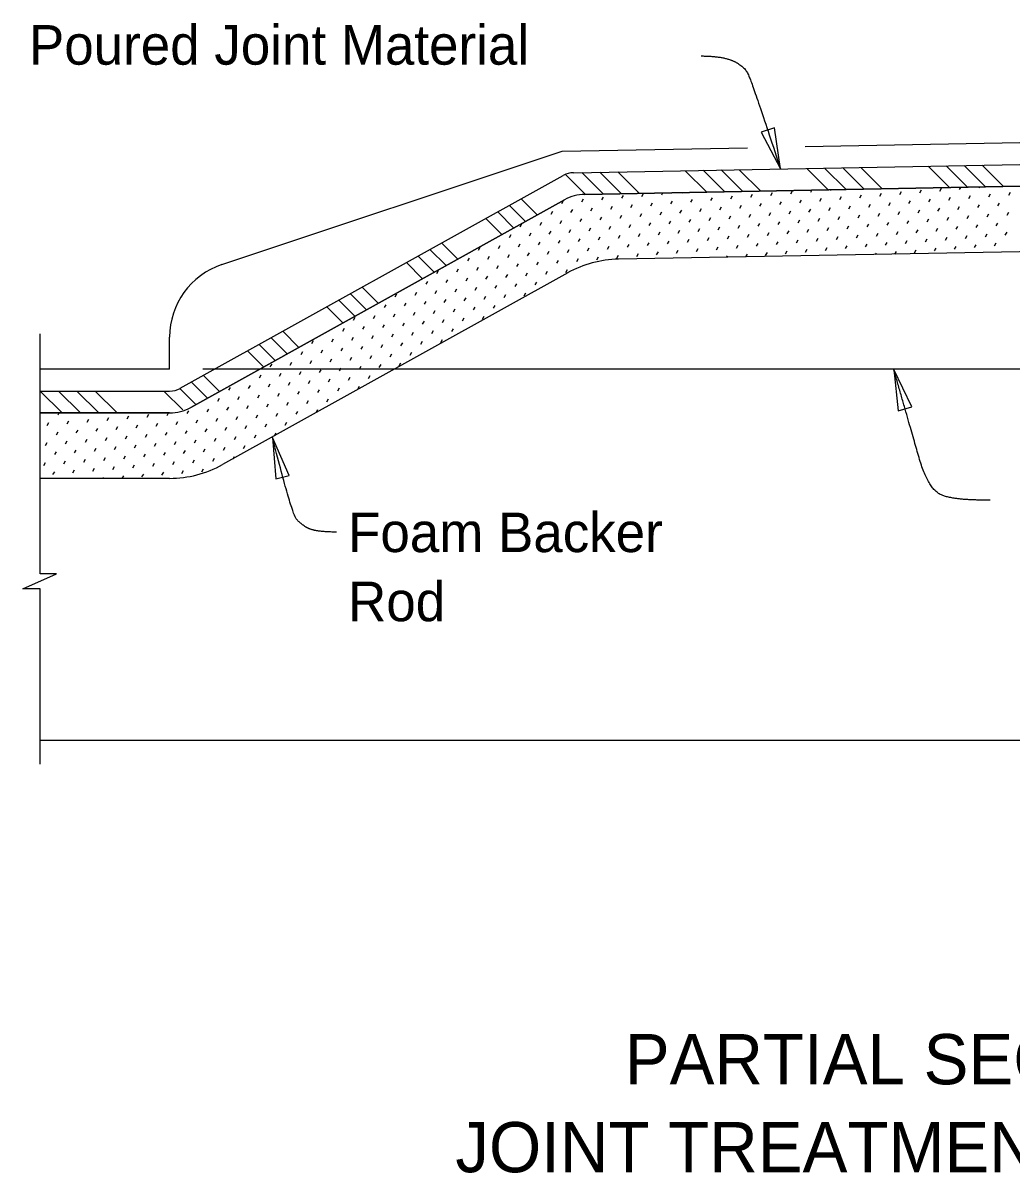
# Model space of a CAD drawing. Extents: x -7.9 to 27, y -3.1 to 14.6.
# Drawn here: x 5.225 to 7.115, y 7.064 to 9.26 of the extents above; entities that cross this region are included whole.
import ezdxf

# ---------------------------------------------------------------- set-up
doc = ezdxf.new("R2010")
doc.units = 0
for name, color, linetype in [('Border', 7, 'Continuous'), ('Patterning', 7, 'Continuous'), ('PlotBorder_dp', 7, 'Continuous'), ('SupstrConc_h', 7, 'Continuous'), ('TextMisc', 7, 'Continuous')]:
    doc.layers.add(name, color=color, linetype=linetype)

msp = doc.modelspace()

# ---------------------------------------------------------------- linework, layer by layer
at = {"layer": 'Patterning'}
for p, q in [((6.7193, 9.0243), (7.7, 9.0424)), ((5.605, 8.7989), (6.2554, 9.0156)), ((6.2554, 9.0157), (6.6094, 9.0222)), ((5.5054, 8.5989), (5.5054, 8.6605)), ((5.2585, 7.8906), (10.1444, 7.8906))]:
    msp.add_line(p, q, dxfattribs=at)
msp.add_lwpolyline([(5.5054, 8.599), (5.2585, 8.599)], dxfattribs=at)
msp.add_arc((5.6512, 8.6606), 0.1458, 108.4349, 180, dxfattribs=at)
at = {"layer": 'PlotBorder_dp'}
for points in [[(6.6724, 8.9817), (6.6606, 9.06), (6.6355, 9.0518)], [(6.8886, 8.5984), (6.8974, 8.5197), (6.9229, 8.527)], [(5.7022, 8.4684), (5.7084, 8.3895), (5.7341, 8.3959)]]:
    msp.add_lwpolyline(points, close=True, dxfattribs=at)
msp.add_lwpolyline([(5.2585, 7.8445), (5.2585, 8.1797), (5.2254, 8.1797), (5.2894, 8.208), (5.2585, 8.208), (5.2585, 8.6664)], dxfattribs=at)
for points in [[(6.5206, 9.1974), (6.5602, 9.1974), (6.6031, 9.1787), (6.6185, 9.1457), (6.6724, 8.9817)], [(7.0728, 8.3491), (7.001, 8.3482), (6.9538, 8.3718), (6.9198, 8.4899), (6.8887, 8.5985)], [(5.8243, 8.288), (5.7847, 8.288), (5.7561, 8.3023), (5.7385, 8.3243), (5.7022, 8.4684)]]:
    msp.add_open_spline(points, degree=2, dxfattribs=at)
at = {"layer": 'SupstrConc_h'}
msp.add_lwpolyline([(9.1821, 8.599), (5.5686, 8.599)], dxfattribs=at)
at = {"layer": 'TextMisc'}
for p, q in [((6.2769, 8.9744), (7.6992, 9.0007)), ((6.8255, 8.9845), (6.8664, 8.9436)), ((6.9542, 8.9869), (6.9952, 8.946)), ((6.9886, 8.9876), (7.0295, 8.9466)), ((7.0229, 8.9882), (7.0639, 8.9472)), ((7.0573, 8.9888), (7.0983, 8.9479)), ((5.5257, 8.5626), (6.2574, 8.9691)), ((6.2623, 8.9704), (6.2996, 8.9331)), ((6.293, 8.9747), (6.334, 8.9337)), ((6.3274, 8.9753), (6.3683, 8.9344)), ((6.3618, 8.9759), (6.4027, 8.935)), ((6.4905, 8.9783), (6.5315, 8.9374)), ((6.5249, 8.979), (6.5658, 8.938)), ((6.5592, 8.9796), (6.6002, 8.9387)), ((6.5936, 8.9802), (6.6346, 8.9393)), ((6.7224, 8.9826), (6.7633, 8.9417)), ((6.7567, 8.9833), (6.7977, 8.9423)), ((6.7911, 8.9839), (6.832, 8.9429)), ((7.6985, 8.959), (6.2985, 8.9331)), ((6.2985, 8.9331), (7.6985, 8.959)), ((6.73, 8.9373), (6.7321, 8.9411)), ((6.7681, 8.9406), (6.7688, 8.9418)), ((6.9382, 8.9361), (6.9414, 8.9417)), ((6.9764, 8.9393), (6.9796, 8.9449)), ((7.0145, 8.9426), (7.0167, 8.9464)), ((7.0527, 8.9458), (7.0534, 8.9471)), ((6.2595, 8.9226), (5.5459, 8.5261)), ((5.5459, 8.5261), (6.2595, 8.9226)), ((6.1771, 8.9245), (6.2077, 8.8938)), ((6.2547, 8.9159), (6.2579, 8.9215)), ((6.2928, 8.9191), (6.2961, 8.9247)), ((6.331, 8.9224), (6.3342, 8.928)), ((6.3691, 8.9256), (6.3724, 8.9312)), ((6.4073, 8.9289), (6.4105, 8.9345)), ((6.4454, 8.9321), (6.4476, 8.9358)), ((6.4629, 8.9147), (6.4661, 8.9202)), ((6.4836, 8.9353), (6.4843, 8.9365)), ((6.501, 8.9179), (6.5043, 8.9235)), ((6.5392, 8.9211), (6.5424, 8.9267)), ((6.5774, 8.9244), (6.5806, 8.93)), ((6.6155, 8.9276), (6.6188, 8.9332)), ((6.6537, 8.9309), (6.6569, 8.9365)), ((6.6711, 8.9134), (6.6744, 8.919)), ((6.6918, 8.9341), (6.6951, 8.9397)), ((6.7093, 8.9166), (6.7125, 8.9222)), ((6.7474, 8.9199), (6.7507, 8.9255)), ((6.7856, 8.9231), (6.7888, 8.9287)), ((6.8237, 8.9264), (6.827, 8.932)), ((6.8619, 8.9296), (6.8651, 8.9352)), ((6.9, 8.9328), (6.9033, 8.9384)), ((6.9175, 8.9154), (6.9207, 8.921)), ((6.9557, 8.9186), (6.9589, 8.9242)), ((6.9938, 8.9219), (6.9971, 8.9275)), ((7.032, 8.9251), (7.0352, 8.9307)), ((7.0701, 8.9284), (7.0734, 8.9339)), ((7.1083, 8.9316), (7.1115, 8.9372)), ((6.1321, 8.8995), (6.1627, 8.8688)), ((6.1546, 8.912), (6.1852, 8.8813)), ((6.234, 8.8952), (6.2372, 8.9008)), ((6.2721, 8.8984), (6.2754, 8.904)), ((6.3103, 8.9017), (6.3135, 8.9073)), ((6.3484, 8.9049), (6.3517, 8.9105)), ((6.3866, 8.9082), (6.3898, 8.9138)), ((6.4247, 8.9114), (6.428, 8.917)), ((6.4422, 8.894), (6.4454, 8.8996)), ((6.4803, 8.8972), (6.4836, 8.9028)), ((6.5185, 8.9004), (6.5217, 8.906)), ((6.5567, 8.9037), (6.5599, 8.9093)), ((6.5948, 8.9069), (6.5981, 8.9125)), ((6.633, 8.9102), (6.6362, 8.9158)), ((6.6504, 8.8927), (6.6537, 8.8983)), ((6.6886, 8.8959), (6.6918, 8.9015)), ((6.7267, 8.8992), (6.73, 8.9048)), ((6.7649, 8.9024), (6.7681, 8.908)), ((6.803, 8.9057), (6.8063, 8.9113)), ((6.8412, 8.9089), (6.8444, 8.9145)), ((6.8587, 8.8914), (6.8619, 8.897)), ((6.8793, 8.9121), (6.8826, 8.9177)), ((6.8968, 8.8947), (6.9, 8.9003)), ((6.935, 8.8979), (6.9382, 8.9035)), ((6.9731, 8.9012), (6.9764, 8.9068)), ((7.0113, 8.9044), (7.0145, 8.91)), ((7.0494, 8.9077), (7.0527, 8.9133)), ((7.0876, 8.9109), (7.0908, 8.9165)), ((7.105, 8.8934), (7.1083, 8.899)), ((6.1096, 8.887), (6.1402, 8.8563)), ((6.1751, 8.8713), (6.1784, 8.8769)), ((6.2133, 8.8745), (6.2165, 8.8801)), ((6.2514, 8.8777), (6.2547, 8.8833)), ((6.2896, 8.881), (6.2928, 8.8866)), ((6.3277, 8.8842), (6.331, 8.8898)), ((6.3659, 8.8875), (6.3691, 8.8931)), ((6.3833, 8.87), (6.3866, 8.8756)), ((6.404, 8.8907), (6.4073, 8.8963)), ((6.4215, 8.8733), (6.4247, 8.8789)), ((6.4597, 8.8765), (6.4629, 8.8821)), ((6.4978, 8.8797), (6.501, 8.8853)), ((6.536, 8.883), (6.5392, 8.8886)), ((6.5741, 8.8862), (6.5774, 8.8918)), ((6.6123, 8.8895), (6.6155, 8.8951)), ((6.6297, 8.872), (6.633, 8.8776)), ((6.6679, 8.8752), (6.6711, 8.8808)), ((6.706, 8.8785), (6.7093, 8.8841)), ((6.7442, 8.8817), (6.7474, 8.8873)), ((6.7823, 8.885), (6.7856, 8.8906)), ((6.8205, 8.8882), (6.8237, 8.8938)), ((6.838, 8.8708), (6.8412, 8.8763)), ((6.8761, 8.874), (6.8793, 8.8796)), ((6.9143, 8.8772), (6.9175, 8.8828)), ((6.9524, 8.8805), (6.9557, 8.8861)), ((6.9906, 8.8837), (6.9938, 8.8893)), ((7.0287, 8.887), (7.032, 8.8926)), ((7.0462, 8.8695), (7.0494, 8.8751)), ((7.0669, 8.8902), (7.0701, 8.8958)), ((7.0843, 8.8727), (7.0876, 8.8783)), ((6.1544, 8.8506), (6.1577, 8.8562)), ((6.1926, 8.8538), (6.1958, 8.8594)), ((6.2307, 8.8571), (6.234, 8.8626)), ((6.2689, 8.8603), (6.2721, 8.8659)), ((6.307, 8.8635), (6.3103, 8.8691)), ((6.3452, 8.8668), (6.3484, 8.8724)), ((6.3626, 8.8493), (6.3659, 8.8549)), ((6.4008, 8.8526), (6.404, 8.8582)), ((6.439, 8.8558), (6.4422, 8.8614)), ((6.4771, 8.859), (6.4803, 8.8646)), ((6.5153, 8.8623), (6.5185, 8.8679)), ((6.5534, 8.8655), (6.5567, 8.8711)), ((6.5709, 8.8481), (6.5741, 8.8537)), ((6.5916, 8.8688), (6.5948, 8.8744)), ((6.609, 8.8513), (6.6123, 8.8569)), ((6.6472, 8.8545), (6.6504, 8.8601)), ((6.6853, 8.8578), (6.6886, 8.8634)), ((6.7235, 8.861), (6.7267, 8.8666)), ((6.7616, 8.8643), (6.7649, 8.8699)), ((6.7998, 8.8675), (6.803, 8.8731)), ((6.8173, 8.8501), (6.8205, 8.8557)), ((6.8554, 8.8533), (6.8587, 8.8589)), ((6.8936, 8.8565), (6.8968, 8.8621)), ((6.9317, 8.8598), (6.935, 8.8654)), ((6.9699, 8.863), (6.9731, 8.8686)), ((7.008, 8.8663), (7.0113, 8.8719)), ((7.0255, 8.8488), (7.0287, 8.8544)), ((7.0636, 8.852), (7.0669, 8.8576)), ((7.1018, 8.8553), (7.105, 8.8609)), ((6.0253, 8.8401), (6.0559, 8.8095)), ((6.0956, 8.8266), (6.0988, 8.8322)), ((6.1337, 8.8299), (6.137, 8.8355)), ((6.1719, 8.8331), (6.1751, 8.8387)), ((6.21, 8.8364), (6.2133, 8.842)), ((6.2482, 8.8396), (6.2514, 8.8452)), ((6.2863, 8.8428), (6.2896, 8.8484)), ((6.3038, 8.8254), (6.307, 8.831)), ((6.3245, 8.8461), (6.3277, 8.8517)), ((6.3419, 8.8286), (6.3452, 8.8342)), ((7.6961, 8.8339), (6.3631, 8.8092)), ((6.3801, 8.8319), (6.3833, 8.8375)), ((6.4183, 8.8351), (6.4215, 8.8407)), ((6.4564, 8.8383), (6.4597, 8.8439)), ((6.4946, 8.8416), (6.4978, 8.8472)), ((6.5327, 8.8448), (6.536, 8.8504)), ((6.5502, 8.8274), (6.5534, 8.833)), ((6.5883, 8.8306), (6.5916, 8.8362)), ((6.6265, 8.8338), (6.6297, 8.8394)), ((6.6646, 8.8371), (6.6679, 8.8427)), ((6.7028, 8.8403), (6.706, 8.8459)), ((6.7409, 8.8436), (6.7442, 8.8492)), ((6.7584, 8.8261), (6.7616, 8.8317)), ((6.7791, 8.8468), (6.7823, 8.8524)), ((6.7966, 8.8294), (6.7998, 8.835)), ((6.8347, 8.8326), (6.838, 8.8382)), ((6.8729, 8.8358), (6.8761, 8.8414)), ((6.911, 8.8391), (6.9143, 8.8447)), ((6.9492, 8.8423), (6.9524, 8.8479)), ((6.9873, 8.8456), (6.9906, 8.8512)), ((7.0048, 8.8281), (7.008, 8.8337)), ((7.0429, 8.8313), (7.0462, 8.8369)), ((7.0811, 8.8346), (7.0843, 8.8402)), ((5.9803, 8.8151), (6.0109, 8.7845)), ((6.0028, 8.8276), (6.0334, 8.797)), ((6.0749, 8.8059), (6.0781, 8.8115)), ((6.113, 8.8092), (6.1163, 8.8148)), ((6.1512, 8.8124), (6.1544, 8.818)), ((6.1893, 8.8157), (6.1926, 8.8213)), ((6.2275, 8.8189), (6.2307, 8.8245)), ((6.2656, 8.8221), (6.2689, 8.8277)), ((6.2831, 8.8047), (6.2863, 8.8103)), ((6.3212, 8.8079), (6.3245, 8.8135)), ((6.3594, 8.8112), (6.3626, 8.8168)), ((6.3976, 8.8144), (6.4008, 8.82)), ((6.4357, 8.8176), (6.439, 8.8232)), ((6.4739, 8.8209), (6.4771, 8.8265)), ((6.512, 8.8241), (6.5153, 8.8297)), ((6.5695, 8.8131), (6.5709, 8.8155)), ((6.6061, 8.8137), (6.609, 8.8187)), ((6.6439, 8.8164), (6.6472, 8.822)), ((6.6821, 8.8196), (6.6853, 8.8252)), ((6.7202, 8.8229), (6.7235, 8.8285)), ((6.854, 8.8183), (6.8554, 8.8207)), ((6.8907, 8.819), (6.8936, 8.824)), ((6.9285, 8.8216), (6.9317, 8.8272)), ((6.9666, 8.8249), (6.9699, 8.8305)), ((5.9578, 8.8026), (5.9884, 8.772)), ((6.016, 8.782), (6.0193, 8.7876)), ((6.0542, 8.7852), (6.0574, 8.7908)), ((6.0923, 8.7885), (6.0956, 8.7941)), ((6.1305, 8.7917), (6.1337, 8.7973)), ((6.1686, 8.795), (6.1719, 8.8006)), ((6.2068, 8.7982), (6.21, 8.8038)), ((6.2449, 8.8014), (6.2482, 8.807)), ((6.2624, 8.784), (6.2656, 8.7896)), ((6.2658, 8.7831), (5.6066, 8.4168)), ((5.9953, 8.7613), (5.9986, 8.7669)), ((6.0335, 8.7645), (6.0367, 8.7701)), ((6.0716, 8.7678), (6.0749, 8.7734)), ((6.1098, 8.771), (6.113, 8.7766)), ((6.1479, 8.7743), (6.1512, 8.7799)), ((6.1861, 8.7775), (6.1893, 8.7831)), ((6.2035, 8.76), (6.2068, 8.7656)), ((6.2242, 8.7807), (6.2275, 8.7863)), ((5.851, 8.7433), (5.8816, 8.7126)), ((5.8735, 8.7558), (5.9041, 8.7251)), ((5.9365, 8.7374), (5.9397, 8.743)), ((5.9746, 8.7406), (5.9779, 8.7462)), ((6.0128, 8.7438), (6.016, 8.7494)), ((6.0509, 8.7471), (6.0542, 8.7527)), ((6.0891, 8.7503), (6.0923, 8.7559)), ((6.1272, 8.7536), (6.1305, 8.7592)), ((6.1654, 8.7568), (6.1686, 8.7624)), ((6.1828, 8.7393), (6.1861, 8.7449)), ((5.8285, 8.7308), (5.8591, 8.7001)), ((5.9158, 8.7167), (5.919, 8.7223)), ((5.9539, 8.7199), (5.9572, 8.7255)), ((5.9921, 8.7231), (5.9953, 8.7287)), ((6.0302, 8.7264), (6.0335, 8.732)), ((6.0684, 8.7296), (6.0716, 8.7352)), ((6.1065, 8.7329), (6.1098, 8.7385)), ((6.124, 8.7154), (6.1272, 8.721)), ((6.1447, 8.7361), (6.1479, 8.7417)), ((5.806, 8.7183), (5.8366, 8.6876)), ((5.8951, 8.696), (5.8983, 8.7016)), ((5.9332, 8.6992), (5.9365, 8.7048)), ((5.9714, 8.7024), (5.9746, 8.708)), ((6.0095, 8.7057), (6.0128, 8.7113)), ((6.0477, 8.7089), (6.0509, 8.7145)), ((6.0858, 8.7122), (6.0891, 8.7178)), ((6.1033, 8.6947), (6.1065, 8.7003)), ((5.8362, 8.672), (5.8395, 8.6776)), ((5.8569, 8.6927), (5.8602, 8.6983)), ((5.8744, 8.6753), (5.8776, 8.6809)), ((5.9125, 8.6785), (5.9158, 8.6841)), ((5.9507, 8.6817), (5.9539, 8.6873)), ((5.9888, 8.685), (5.9921, 8.6906)), ((6.027, 8.6882), (6.0302, 8.6938)), ((6.0651, 8.6915), (6.0684, 8.6971)), ((5.6992, 8.659), (5.7298, 8.6283)), ((5.7217, 8.6715), (5.7523, 8.6408)), ((5.8155, 8.6513), (5.8188, 8.6569)), ((5.8537, 8.6546), (5.8569, 8.6602)), ((5.8918, 8.6578), (5.8951, 8.6634)), ((5.93, 8.6611), (5.9332, 8.6666)), ((5.9681, 8.6643), (5.9714, 8.6699)), ((6.0063, 8.6675), (6.0095, 8.6731)), ((6.0237, 8.6501), (6.027, 8.6557)), ((6.0444, 8.6708), (6.0477, 8.6764)), ((5.6542, 8.634), (5.6848, 8.6033)), ((5.6767, 8.6465), (5.7073, 8.6158)), ((5.7567, 8.6274), (5.7599, 8.633)), ((5.7774, 8.6481), (5.7806, 8.6537)), ((5.7948, 8.6306), (5.7981, 8.6362)), ((5.833, 8.6339), (5.8362, 8.6395)), ((5.8711, 8.6371), (5.8744, 8.6427)), ((5.9093, 8.6404), (5.9125, 8.646)), ((5.9474, 8.6436), (5.9507, 8.6492)), ((5.9856, 8.6468), (5.9888, 8.6524)), ((5.736, 8.6067), (5.7392, 8.6123)), ((5.7741, 8.6099), (5.7774, 8.6155)), ((5.8123, 8.6132), (5.8155, 8.6188)), ((5.8504, 8.6164), (5.8537, 8.622)), ((5.8886, 8.6197), (5.8918, 8.6253)), ((5.9267, 8.6229), (5.93, 8.6285)), ((5.9442, 8.6054), (5.9474, 8.611)), ((5.9649, 8.6261), (5.9681, 8.6317)), ((5.6978, 8.6035), (5.7011, 8.609)), ((5.7153, 8.586), (5.7185, 8.5916)), ((5.7534, 8.5892), (5.7567, 8.5948)), ((5.7916, 8.5925), (5.7948, 8.5981)), ((5.8297, 8.5957), (5.833, 8.6013)), ((5.8679, 8.599), (5.8711, 8.6046)), ((5.906, 8.6022), (5.9093, 8.6078)), ((5.5474, 8.5746), (5.578, 8.5439)), ((5.5699, 8.5871), (5.6005, 8.5564)), ((5.6564, 8.5621), (5.6597, 8.5677)), ((5.6771, 8.5828), (5.6804, 8.5884)), ((5.6946, 8.5653), (5.6978, 8.5709)), ((5.7327, 8.5685), (5.736, 8.5741)), ((5.7709, 8.5718), (5.7741, 8.5774)), ((5.809, 8.575), (5.8123, 8.5806)), ((5.8472, 8.5783), (5.8504, 8.5839)), ((5.8853, 8.5815), (5.8886, 8.5871)), ((5.2585, 8.5156), (5.2585, 8.5573)), ((5.2585, 8.5573), (5.5054, 8.5573)), ((5.2585, 8.5573), (5.3002, 8.5156)), ((5.2935, 8.5573), (5.3352, 8.5156)), ((5.3285, 8.5573), (5.3702, 8.5156)), ((5.3635, 8.5573), (5.4052, 8.5156)), ((5.4947, 8.5573), (5.5307, 8.5213)), ((5.5247, 8.5623), (5.5555, 8.5314)), ((5.6183, 8.5588), (5.6215, 8.5644)), ((5.6357, 8.5414), (5.639, 8.547)), ((5.6739, 8.5446), (5.6771, 8.5502)), ((5.712, 8.5478), (5.7153, 8.5534)), ((5.7502, 8.5511), (5.7534, 8.5567)), ((5.7883, 8.5543), (5.7916, 8.5599)), ((5.8265, 8.5576), (5.8297, 8.5632)), ((5.8647, 8.5608), (5.8679, 8.5664)), ((5.5976, 8.5381), (5.6008, 8.5437)), ((5.615, 8.5207), (5.6183, 8.5263)), ((5.6532, 8.5239), (5.6564, 8.5295)), ((5.6913, 8.5271), (5.6946, 8.5327)), ((5.7295, 8.5304), (5.7327, 8.536)), ((5.7676, 8.5336), (5.7709, 8.5392)), ((5.8058, 8.5369), (5.809, 8.5425)), ((5.5054, 8.5156), (5.2585, 8.5156)), ((5.2585, 8.3906), (5.2585, 8.5156)), ((5.2585, 8.5156), (5.5054, 8.5156)), ((5.2923, 8.5122), (5.2943, 8.5156)), ((5.3305, 8.5154), (5.3306, 8.5156)), ((5.3479, 8.498), (5.3512, 8.5036)), ((5.3861, 8.5012), (5.3893, 8.5068)), ((5.4243, 8.5045), (5.4275, 8.5101)), ((5.4624, 8.5077), (5.4657, 8.5133)), ((5.5006, 8.5109), (5.5033, 8.5156)), ((5.5387, 8.5142), (5.542, 8.5198)), ((5.5562, 8.4967), (5.5594, 8.5023)), ((5.5769, 8.5174), (5.5801, 8.523)), ((5.5943, 8.5), (5.5976, 8.5056)), ((5.6325, 8.5032), (5.6357, 8.5088)), ((5.6706, 8.5064), (5.6739, 8.512)), ((5.7088, 8.5097), (5.712, 8.5153)), ((5.7469, 8.5129), (5.7502, 8.5185)), ((5.7851, 8.5162), (5.7883, 8.5218)), ((5.2716, 8.4915), (5.2749, 8.4971)), ((5.2891, 8.474), (5.2923, 8.4796)), ((5.3098, 8.4947), (5.313, 8.5003)), ((5.3272, 8.4773), (5.3305, 8.4829)), ((5.3654, 8.4805), (5.3686, 8.4861)), ((5.4036, 8.4838), (5.4068, 8.4894)), ((5.4417, 8.487), (5.445, 8.4926)), ((5.4799, 8.4902), (5.4831, 8.4958)), ((5.518, 8.4935), (5.5213, 8.4991)), ((5.5355, 8.476), (5.5387, 8.4816)), ((5.5736, 8.4793), (5.5769, 8.4849)), ((5.6118, 8.4825), (5.615, 8.4881)), ((5.6499, 8.4857), (5.6532, 8.4913)), ((5.6881, 8.489), (5.6913, 8.4946)), ((5.7262, 8.4922), (5.7295, 8.4978)), ((5.2684, 8.4533), (5.2716, 8.4589)), ((5.3066, 8.4566), (5.3098, 8.4622)), ((5.3447, 8.4598), (5.3479, 8.4654)), ((5.3829, 8.4631), (5.3861, 8.4687)), ((5.421, 8.4663), (5.4243, 8.4719)), ((5.4592, 8.4695), (5.4624, 8.4751)), ((5.4766, 8.4521), (5.4799, 8.4577)), ((5.4973, 8.4728), (5.5006, 8.4784)), ((5.5148, 8.4553), (5.518, 8.4609)), ((5.5529, 8.4586), (5.5562, 8.4642)), ((5.5911, 8.4618), (5.5943, 8.4674)), ((5.6292, 8.465), (5.6325, 8.4706)), ((5.6674, 8.4683), (5.6706, 8.4739)), ((5.7058, 8.4719), (5.7088, 8.4771)), ((5.2859, 8.4359), (5.2891, 8.4415)), ((5.324, 8.4391), (5.3272, 8.4447)), ((5.3622, 8.4424), (5.3654, 8.448)), ((5.4003, 8.4456), (5.4036, 8.4512)), ((5.4385, 8.4488), (5.4417, 8.4544)), ((5.4559, 8.4314), (5.4592, 8.437)), ((5.4941, 8.4346), (5.4973, 8.4402)), ((5.5322, 8.4379), (5.5355, 8.4435)), ((5.5704, 8.4411), (5.5736, 8.4467)), ((5.6085, 8.4444), (5.6118, 8.4499)), ((5.6467, 8.4476), (5.6499, 8.4532)), ((5.2652, 8.4152), (5.2684, 8.4208)), ((5.3033, 8.4184), (5.3066, 8.424)), ((5.3415, 8.4217), (5.3447, 8.4273)), ((5.3796, 8.4249), (5.3829, 8.4305)), ((5.4178, 8.4281), (5.421, 8.4337)), ((5.4352, 8.4107), (5.4385, 8.4163)), ((5.4734, 8.4139), (5.4766, 8.4195)), ((5.5115, 8.4172), (5.5148, 8.4228)), ((5.5497, 8.4204), (5.5529, 8.426)), ((5.5878, 8.4237), (5.5911, 8.4293)), ((5.6266, 8.4279), (5.6292, 8.4325)), ((5.2826, 8.3977), (5.2859, 8.4033)), ((5.3208, 8.401), (5.324, 8.4066)), ((5.3589, 8.4042), (5.3622, 8.4098)), ((5.3786, 8.3906), (5.3796, 8.3923)), ((5.3971, 8.4074), (5.4003, 8.413)), ((5.4149, 8.3906), (5.4178, 8.3956)), ((5.4527, 8.3932), (5.4559, 8.3988)), ((5.4908, 8.3965), (5.4941, 8.4021)), ((5.529, 8.3997), (5.5322, 8.4053)), ((5.5671, 8.403), (5.5704, 8.4086)), ((5.5054, 8.3906), (5.2585, 8.3906))]:
    msp.add_line(p, q, dxfattribs=at)
for centre, radius, start, end in [((6.2777, 8.9327), 0.0417, 91.0616, 119.0562), ((6.3, 8.8498), 0.0833, 91.0616, 119.0562), ((6.3, 8.8498), 0.0833, 91.0616, 119.0562), ((6.3669, 8.601), 0.2083, 91.0616, 119.0562), ((5.5054, 8.599), 0.0417, 269.9997, 299.0562), ((5.5054, 8.5989), 0.0833, 269.9997, 299.0562), ((5.5054, 8.5989), 0.0833, 269.9997, 299.0562), ((5.5054, 8.5989), 0.2083, 269.9997, 299.0562)]:
    msp.add_arc(centre, radius, start, end, dxfattribs=at)

# ---------------------------------------------------------------- texts
at = {"layer": 'Border'}
msp.add_text('Poured Joint Material', height=0.0756, dxfattribs=at).set_placement((5.2368, 9.1808))
at = {"layer": 'PlotBorder_dp'}
for s, height, p in [('Foam Backer ', 0.0756, (5.8463, 8.2497)), ('Rod', 0.0756, (5.8463, 8.1177)), ('PARTIAL SECTION ALONG ℄ JOINT,', 0.096, (6.3749, 7.2331)), ('JOINT TREATMENT AT TRAFFIC SEPARATOR', 0.096, (6.0513, 7.0651))]:
    msp.add_text(s, height=height, dxfattribs=at).set_placement(p)

doc.saveas('drawing.dxf')
